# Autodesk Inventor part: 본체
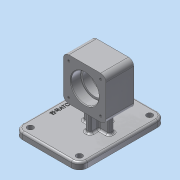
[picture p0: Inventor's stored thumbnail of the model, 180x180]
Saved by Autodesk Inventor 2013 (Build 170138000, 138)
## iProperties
Created: 2020-11
Part Number: 본체
Material: 알루미늄 6061
Document SubType Name: Modeling
Designer: user
Density: 1 g/cm^3
Author: user
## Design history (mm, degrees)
sketch "스케치1"
  geometry: L1 (-65, -49)-(65, -49); L2 (65, -49)-(65, 49); L3 (65, 49)-(-65, 49); L4 (-65, 49)-(-65, -49); L5 (-65, -49)-(65, 49); L6 (65, -49)-(-65, 49); 1 further point
  constraints: 12 end point, 2 midpoint, 2 parallel, 1 horizontal, 1 perpendicular
  dimensions: "d0" = 130 distance of L3.end L2.end; "d1" = 98 distance of L2.end L1.end
extrude "돌출1" new body sketch "스케치1" distance "d2" = 10; taper "d3" = 0 deg
node "작업 평면2"
sketch "스케치2"
  geometry: L1 (-65, 0)-(-65, 10) reference; L2 (-65, 10)-(65, 10) reference; L3 (65, 10)-(65, 0) reference; L4 (65, 0)-(-65, 0) reference; L5 (21, 38)-(-21, 38); L6 (-21, 38)-(-21, 102); L7 (-21, 102)-(21, 102); L8 (21, 102)-(21, 38); L9 (21, 70)-(-21, 70); 3 further points
  constraints: 10 end point, 4 midpoint, 3 parallel, 1 perpendicular, 1 vertical alignment
  dimensions: "d9" = 64 distance between parallel lines of L5 L7; "d10" = 70 distance between parallel lines of L4 L9; "d11" = 42 distance of L6.end L7.end
extrude "돌출2" join sketch "스케치2" stored distance "d12" = 64; taper "d13" = 0 deg
sketch "스케치3"
  geometry: L1 (-65, 0)-(-65, 10) reference; L2 (-65, 10)-(65, 10) reference; L3 (65, 10)-(65, 0) reference; L4 (65, 0)-(-65, 0) reference; L5 (-21, 38)-(-21, 102) reference; L6 (-21, 102)-(21, 102) reference; L7 (21, 102)-(21, 38) reference; L8 (21, 38)-(-21, 38) reference; L9 (21, 91)-(6.3, 91); L10 (6, 90.7)-(6, 88); L11 (6, 88)-(-6, 88); L12 (-6, 88)-(-6, 90.7); L13 (-6.3, 91)-(-21, 91); L14 (21, 70)-(-21, 70); L15 (-21, 70)-(-21, 91); L16 (21, 91)-(21, 70); A1 r 0.3 centre (6.3, 90.7) between (6.3, 91) and (6, 90.7); A2 r 0.3 centre (-6.3, 90.7) between (-6, 90.7) and (-6.3, 91); 1 further point
  constraints: 16 end point, 4 point on circle, 4 tangent, 3 perpendicular, 2 centre point, 2 collinear, 2 midpoint, 2 parallel, 2 point on line, 1 equal radius
  dimensions: "d14" = 42 diameter of L13 L14; "d16" = 36 diameter of L11 L14; "d17" = 42 diameter of L9 L14; "d19" = 15 distance between parallel lines of L15 L12; "d20" = 0.3 radius of A1; "d21" = 15 distance between parallel lines of L16 L10
revolve "회전1" sketch "스케치3" stored, may be unused: angle "d22" = 90 deg
chamfer "모따기1" distance "d23" = 1; stored, may be unused: second distance "d24" = 2, angle "d25" = 45 deg
fillet "모깎기1" dims "d26" = 8
sketch "스케치4"
  geometry: A1 r 8 centre (8, 48) between (8, 56) and (0, 48) reference; A2 r 8 centre (8, 0) between (0, 0) and (8, -8) reference; A3 r 8 centre (56, 0) between (56, -8) and (64, 0) reference; A4 r 8 centre (56, 48) between (64, 48) and (56, 56) reference; 1 further point
hole "구멍1" sketch "스케치4" at (56, 48), (56, 0), (8, 0), (8, 48) diameter "d27" = 3.242; stored, may be unused: countersink angle "d31" = 90 deg, drill point angle "d33" = 118 deg; dims "d28" = 8, "d29" = 4, "d30" = 2, "d32" = 10
sketch "스케치5"
  geometry: A1 r 8 centre (56, 48) between (64, 48) and (56, 56) reference; A2 r 8 centre (8, 48) between (8, 56) and (0, 48) reference; A3 r 8 centre (8, 0) between (0, 0) and (8, -8) reference; A4 r 8 centre (56, 0) between (56, -8) and (64, 0) reference; 1 further point
hole "구멍2" sketch "스케치5" at (8, 0), (8, 48), (56, 48), (56, 0) diameter "d34" = 3.242; stored, may be unused: countersink angle "d38" = 90 deg, drill point angle "d40" = 118 deg; dims "d35" = 8, "d36" = 4, "d37" = 2, "d39" = 10
fillet "모깎기2" dims "d41" = 12
fillet "모깎기3" dims "d42" = 3
sketch "스케치6"
  geometry: A1 r 9 centre (-53, -37) between (-62, -37) and (-53, -46) reference; A2 r 9 centre (53, -37) between (53, -46) and (62, -37) reference; A3 r 9 centre (53, 37) between (62, 37) and (53, 46) reference; A4 r 9 centre (-53, 37) between (-53, 46) and (-62, 37) reference; 1 further point
hole "구멍3" sketch "스케치6" at (-53, 37), (-53, -37), (53, -37), (53, 37) diameter "d43" = 9; stored, may be unused: countersink angle "d47" = 90 deg, drill point angle "d49" = 118 deg; dims "d44" = 8, "d45" = 4, "d46" = 2, "d48" = 10
sketch "스케치7"
  geometry: L1 (-17, -17)-(-4, -17); L2 (17, -17)-(17, -9); L3 (17, -9)-(4, -9); L4 (-17, -9)-(-17, -17); L5 (-17, -17)-(17, -9); L6 (17, -17)-(-17, -9); L7 (53, 49)-(-53, 49) reference; L8 (-4, -33)-(4, -33); L9 (4, -33)-(4, -17); L10 (4, 7)-(-4, 7); L11 (-4, 7)-(-4, -9); L12 (-4, -33)-(4, 7); L13 (4, -33)-(-4, 7); L14 (-4, -9)-(-4, -17); L15 (-4, -17)-(-4, -33); L16 (-4, -17)-(4, -17); L17 (4, -17)-(17, -17); L18 (4, -9)-(4, 7); L19 (-4, -9)-(-17, -9); L20 (4, -9)-(-4, -9); L21 (4, -17)-(4, -9); 3 further points
  constraints: 40 end point, 20 parallel, 6 perpendicular, 5 midpoint, 4 horizontal, 1 vertical alignment
  dimensions: "d50" = 34 distance of L4.start L2.end; "d51" = 8 distance of L2.end L2.start; "d52" = 62 distance from line of L7 point (0, -13); "d53" = 8 distance of L10.end L10.start; "d54" = 40 distance of L10.start L8.end
extrude "돌출3" join sketch "스케치7" stored distance "d55" = 10; taper "d56" = 0 deg
fillet "모깎기4" dims "d57" = 3
fillet "모깎기5" dims "d58" = 3
sketch "스케치8"
  geometry: L1 (-24.383, 40.013)-(24.383, 40.013); L2 (24.383, 40.013)-(24.383, 37.987); L3 (24.383, 37.987)-(-24.383, 37.987); L4 (-24.383, 37.987)-(-24.383, 40.013); L5 (-24.383, 39)-(24.383, 39); L6 (0, 40.013)-(0, 37.987); L7 (65, -37)-(65, 37) reference; L8 (53, 49)-(-53, 49) reference; 1 further point
  constraints: 4 end point, 4 midpoint, 2 other
  dimensions: "d59" = 65 distance from line of L7 L6.start; "d60" = 10 distance between parallel lines of L5 L8
feature "엠보싱1" sketch "스케치8" dims "d0" = 130, "d1" = 98, "d61" = 0.5, "d62" = 0
node "솔리드1"
node "절단 모서리 투영1"
node "절단 모서리 투영2"
other parameters: "d4" = -13
